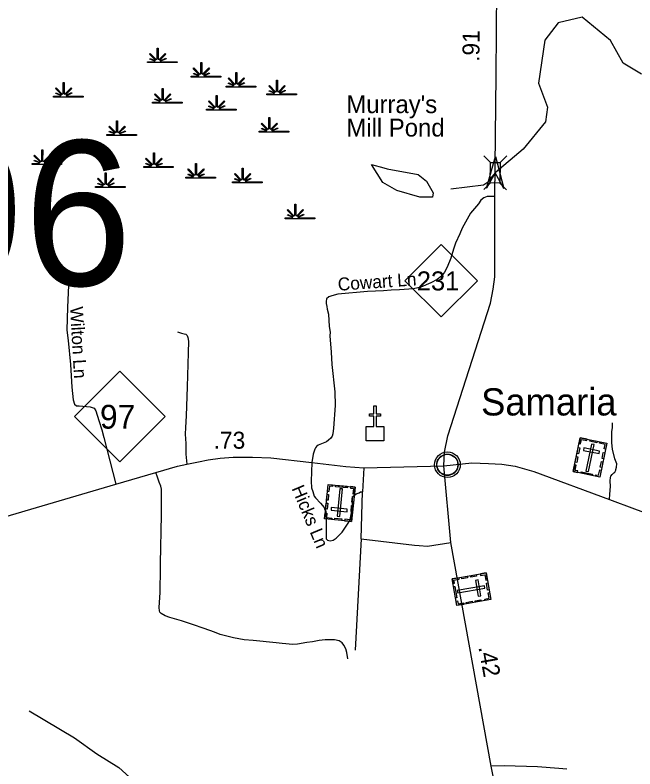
# Model space of a CAD drawing. Extents: x 2220236 to 2384410, y 720751 to 894131.
# Drawn here: x 2240252 to 2244809, y 766678 to 772223 of the extents above; entities that cross this region are included whole.
import ezdxf

# ---------------------------------------------------------------- set-up
doc = ezdxf.new("R2010")
doc.units = 0
doc.layers.add('Default', color=7, linetype='Continuous')

msp = doc.modelspace()

# ---------------------------------------------------------------- linework, layer by layer
at = {"layer": 'Default'}
for p, q in [((2243698.6, 771188.3), (2243747, 771139.1)), ((2243866.8, 771186.9), (2243817.6, 771138.5)), ((2243747, 770988), (2243697.8, 770939.6)), ((2243816, 770987.4), (2243864.4, 770938.2)), ((2242816.7, 768892.5), (2242807.2, 768717.3)), ((2242796.1, 768371.4), (2242807.2, 768717.3)), ((2242796.1, 768371.4), (2242752.9, 767551.3))]:
    msp.add_line(p, q, dxfattribs=at)
for points in [[(2243782.4, 771111.2), (2243790, 771781), (2243793, 772421.1), (2243791, 773115.5), (2243793, 773383.4), (2243759.6, 773678)], [(2244856.2, 771788.5), (2244722.3, 771870), (2244629.2, 772035.9), (2244420.2, 772207.4), (2244245.3, 772165.1), (2244146.3, 772039.2), (2244099.3, 771722.1), (2244167.2, 771546.8), (2244151.2, 771438.9), (2243987.3, 771236.8), (2243782.1, 771061.9), (2243748.1, 771021.8), (2243725.1, 770992.6), (2243695.9, 770973.2), (2243455.2, 770941.5)], [(2243228.6, 770884.2), (2243059, 770932.3), (2242956.1, 770991.4), (2242873.2, 771124.6), (2242963.6, 771100.2), (2242987, 771093.2), (2243215.7, 771050.7), (2243275.7, 771002.5), (2243327, 770915.6), (2243321.1, 770884.3), (2243228.6, 770884.2)], [(2243404.2, 768908.5), (2243410, 769007.2), (2243433.2, 769129.1), (2243746.5, 770104.5), (2243766.8, 770207.6), (2243778.1, 770298.5), (2243779.9, 770888.3), (2243782.4, 771111.2)], [(2243779.9, 770888.3), (2243741.3, 770889.9), (2243723.3, 770889.9), (2243699.3, 770879.6), (2243676.9, 770862.2), (2243659.8, 770835.4), (2243600.3, 770764.9), (2243539.1, 770656.6), (2243521.6, 770614.3), (2243490.1, 770546.2), (2243474.5, 770501.9), (2243455, 770435.9), (2243427.6, 770369.7), (2243407.9, 770331.5), (2243388.1, 770303.4), (2243356.4, 770279.2), (2243308.5, 770254.8), (2243234.9, 770222.1), (2243181, 770209.8), (2243077.1, 770201), (2243017.1, 770200.4), (2242961.2, 770194), (2242843.3, 770191), (2242625.6, 770171.3), (2242579.7, 770158.8), (2242557.8, 770150.7), (2242541.9, 770136.6), (2242538.1, 770116.5), (2242538.1, 770100.5), (2242544.3, 770080.6), (2242546.5, 770058.7), (2242556.7, 770022.7), (2242561.5, 769932.8), (2242567.8, 769890.9), (2242566.1, 769863), (2242577, 769743), (2242581.7, 769653.1), (2242603.4, 769451.3), (2242604.3, 769351.3), (2242593.5, 769185.4), (2242588, 769143.3), (2242582.1, 769125.4), (2242574.2, 769111.2), (2242556.3, 769095.2), (2242540.5, 769085.1), (2242480.7, 769058.5), (2242468.8, 769050.4), (2242460.8, 769040.3), (2242455, 769030.3), (2242443.2, 768994.3), (2242433.7, 768932.1)], [(2240673.3, 770319.1), (2240645.5, 770234.1), (2240638.6, 770074.6), (2240631.7, 769904.6), (2240642.1, 769828.3), (2240659.4, 769653.1), (2240669.8, 769484.9), (2240678.5, 769393), (2240688.9, 769361.8), (2240702.7, 769349.6), (2240723.5, 769347.9), (2240805, 769341), (2240834.4, 769330.6), (2240846.6, 769311.5), (2240869.1, 769240.4), (2240889.9, 769172.7), (2240903.8, 769115.5), (2240991.9, 768772.1)], [(2241447.4, 769892.6), (2241476.4, 769882.4), (2241495.3, 769879.5), (2241508.3, 769875.2), (2241517, 769866.5), (2241522.8, 769850.5), (2241527.2, 769824.4), (2241525.7, 769738.7), (2241517, 769487.6), (2241511.2, 769275.7), (2241504, 769190.1), (2241502.5, 769140.7), (2241506.9, 769072.5), (2241508.3, 768992.7), (2241515.4, 768919.7)], [(2244622.8, 768660.2), (2244625.6, 768699.5), (2244628.5, 768756.1), (2244627, 768796.8), (2244628.5, 768821.4), (2244632.8, 768831.6), (2244641.5, 768844.6), (2244654.6, 768854.8), (2244660.4, 768860.6), (2244669.1, 768875.1), (2244669.1, 768879.5), (2244673.4, 768898.4), (2244674.9, 768923), (2244660.4, 768957.9), (2244643, 769029), (2244640.1, 769076.9), (2244638.6, 769123.3), (2244640.1, 769161.1), (2244644.4, 769187.2), (2244643, 769223.5)], [(2239633.6, 768371.7), (2240991.9, 768772.1), (2241286.5, 768858.8), (2241447.4, 768905.6), (2241515.4, 768919.7), (2241601.2, 768937.5), (2241672.3, 768952.1), (2241760.7, 768963.7), (2241855, 768970.9), (2241998.6, 768970.9), (2242133.5, 768966.6), (2242433.7, 768932.1), (2242683.3, 768901.3), (2242816.7, 768892.5), (2243404.2, 768908.5)], [(2242433.7, 768932.1), (2242430.3, 768862.2), (2242428.9, 768794.3), (2242431.3, 768746.2), (2242441.5, 768718.4), (2242445.6, 768700.3), (2242451.6, 768684.4), (2242459.8, 768672.5), (2242498.2, 768632.9), (2242524.3, 768601.1), (2242530.5, 768583.2), (2242536.7, 768571.1), (2242538.9, 768543.3), (2242540.2, 768371.3), (2242548.4, 768361.3), (2242568.4, 768355.5), (2242590.4, 768361.6), (2242612.3, 768375.8), (2242657.9, 768418.2), (2242705.2, 768492.7), (2242715, 768512.6), (2242716.9, 768524.6), (2242726.6, 768560.8), (2242732.1, 768630.7), (2242731.8, 768666.7), (2242733.8, 768674.8), (2242743.6, 768686.8), (2242759.5, 768700.9), (2242781.5, 768709), (2242791.4, 768715.2), (2242807.2, 768717.3)], [(2243404.2, 768908.5), (2243610.2, 768928.8), (2243732, 768924.5), (2243830.7, 768920.1), (2243927.4, 768904.4), (2244065.7, 768866.4), (2244622.8, 768660.2), (2244806.9, 768592.1), (2245412.9, 768366.8), (2245599.2, 768318.2), (2245769.6, 768287.7), (2245889, 768269.9), (2246369.1, 768222), (2246940.6, 768169.7), (2247148.1, 768147.9), (2247220.6, 768137.8)], [(2243752.3, 766697.9), (2243456.1, 768342.8), (2243404.2, 768908.5)], [(2242699.2, 767487.5), (2242690.5, 767535.4), (2242683.3, 767561.6), (2242668.8, 767589.1), (2242655.7, 767606.5), (2242635.4, 767621.1), (2242600.6, 767628.3), (2242565.8, 767628.3), (2242532.4, 767626.9), (2242487.5, 767622.5), (2242438.1, 767613.8), (2242397.5, 767608), (2242327.9, 767596.4), (2242293.1, 767593.5), (2242216.2, 767599.3), (2242172.7, 767605.1), (2242001.5, 767622.5), (2241936.3, 767628.3), (2241857.9, 767641.4), (2241759.3, 767666.1), (2241717.2, 767683.5), (2241641.8, 767711.1), (2241557.7, 767740.1), (2241475, 767766.2), (2241389.4, 767792.3), (2241356, 767803.9), (2241327, 767819.9), (2241315.4, 767831.5), (2241314, 767840.2), (2241312.5, 767864.9), (2241319.8, 767975.2), (2241321.2, 768158.1), (2241321.2, 768190), (2241328.5, 768547.1), (2241329.9, 768689.3), (2241328.5, 768735.8), (2241324.1, 768757.6), (2241312.5, 768788), (2241299.5, 768824.3), (2241286.5, 768858.8)], [(2242796.1, 768371.4), (2243188.2, 768324.6), (2243222.4, 768320.9), (2243284.3, 768317.4), (2243456.1, 768342.8)], [(2240355.2, 767104.1), (2240690.1, 766907.5), (2240852.8, 766787.7), (2241015.3, 766689.1), (2241147.7, 766567.9)], [(2244309.2, 766676.5), (2244249.3, 766680), (2244093.2, 766692.1), (2243846.6, 766700.8), (2243752.3, 766697.9)], [(2243864.7, 759641.9), (2243930.1, 759702.3), (2243971.8, 759748.6), (2244043.1, 759833.1), (2244135.7, 759980), (2244188.7, 760122.3), (2244207.7, 760224.5), (2244220.4, 760402.3), (2244214.3, 760650.2), (2244209.5, 761477.9), (2244171.3, 761857.2), (2244130, 762281.7), (2244088.7, 762603.9), (2244012.1, 763641.4), (2243951.6, 764595.7), (2243901.8, 765403.6), (2243865.9, 765885.2), (2243845.9, 766119), (2243807.7, 766418.5), (2243752.3, 766697.9)]]:
    msp.add_lwpolyline(points, dxfattribs=at)
for points in [[(2241226, 771880.4), (2241278.7, 771880.5), (2241280.7, 771884.1), (2241242.4, 771898.9), (2241245.3, 771904.1), (2241283, 771888.3), (2241284.6, 771891.2), (2241240.2, 771935.8), (2241245.3, 771940.9), (2241290.6, 771895.4), (2241297, 771897.8), (2241297, 771980.9), (2241304.2, 771980.9), (2241304.2, 771897.8), (2241310.5, 771895.4), (2241355.8, 771940.9), (2241361, 771935.8), (2241316.5, 771891.2), (2241318.5, 771887.6), (2241359.4, 771906.2), (2241361.9, 771901.2), (2241320.9, 771883.4), (2241322.5, 771880.5), (2241443.5, 771880.4), (2241443.5, 771873.3), (2241226, 771873.3)], [(2241546.5, 771773.4), (2241599.2, 771773.5), (2241601.2, 771777.1), (2241562.9, 771792), (2241565.8, 771797.1), (2241603.5, 771781.4), (2241605.1, 771784.3), (2241560.7, 771828.8), (2241565.8, 771834), (2241611.1, 771788.5), (2241617.5, 771790.9), (2241617.5, 771873.9), (2241624.7, 771873.9), (2241624.7, 771790.9), (2241631, 771788.5), (2241676.3, 771834), (2241681.4, 771828.8), (2241637, 771784.3), (2241639, 771780.7), (2241679.9, 771799.3), (2241682.4, 771794.2), (2241641.4, 771776.4), (2241643, 771773.5), (2241764, 771773.4), (2241764, 771766.3), (2241546.5, 771766.3)], [(2241803.5, 771700.4), (2241856.2, 771700.5), (2241858.2, 771704.1), (2241819.9, 771719), (2241822.8, 771724.1), (2241860.6, 771708.4), (2241862.2, 771711.3), (2241817.7, 771755.8), (2241822.9, 771761), (2241868.1, 771715.5), (2241874.5, 771717.9), (2241874.5, 771800.9), (2241881.7, 771800.9), (2241881.7, 771717.9), (2241888, 771715.5), (2241933.3, 771761), (2241938.5, 771755.8), (2241894, 771711.3), (2241896, 771707.7), (2241936.9, 771726.3), (2241939.4, 771721.3), (2241898.4, 771703.4), (2241900, 771700.5), (2242021.1, 771700.4), (2242021.1, 771693.3), (2241803.5, 771693.3)], [(2240534.4, 771627.1), (2240587.1, 771627.2), (2240589.1, 771630.8), (2240550.8, 771645.6), (2240553.7, 771650.8), (2240591.4, 771635.1), (2240593, 771637.9), (2240548.6, 771682.5), (2240553.7, 771687.6), (2240599, 771642.1), (2240605.4, 771644.5), (2240605.4, 771727.6), (2240612.6, 771727.6), (2240612.6, 771644.5), (2240618.9, 771642.1), (2240664.2, 771687.6), (2240669.4, 771682.5), (2240624.9, 771637.9), (2240626.9, 771634.3), (2240667.8, 771652.9), (2240670.3, 771647.9), (2240629.3, 771630.1), (2240630.9, 771627.2), (2240751.9, 771627.1), (2240751.9, 771620), (2240534.4, 771620)], [(2242103.2, 771644), (2242155.8, 771644.1), (2242157.8, 771647.7), (2242119.6, 771662.5), (2242122.5, 771667.7), (2242160.2, 771651.9), (2242161.8, 771654.8), (2242117.4, 771699.4), (2242122.5, 771704.5), (2242167.8, 771659), (2242174.1, 771661.4), (2242174.1, 771744.5), (2242181.4, 771744.5), (2242181.3, 771661.4), (2242187.7, 771659), (2242233, 771704.5), (2242238.1, 771699.4), (2242193.7, 771654.8), (2242195.7, 771651.2), (2242236.6, 771669.8), (2242239, 771664.8), (2242198, 771647), (2242199.7, 771644.1), (2242320.7, 771644), (2242320.7, 771636.9), (2242103.2, 771636.9)], [(2241263.1, 771583.4), (2241315.8, 771583.5), (2241317.8, 771587.1), (2241279.5, 771601.9), (2241282.4, 771607.1), (2241320.1, 771591.4), (2241321.7, 771594.2), (2241277.3, 771638.8), (2241282.4, 771643.9), (2241327.7, 771598.4), (2241334.1, 771600.8), (2241334.1, 771683.9), (2241341.3, 771683.9), (2241341.3, 771600.8), (2241347.6, 771598.4), (2241392.9, 771643.9), (2241398.1, 771638.8), (2241353.6, 771594.2), (2241355.6, 771590.6), (2241396.5, 771609.2), (2241399, 771604.2), (2241358, 771586.4), (2241359.6, 771583.5), (2241480.6, 771583.4), (2241480.6, 771576.3), (2241263.1, 771576.3)], [(2241659, 771531.4), (2241711.6, 771531.5), (2241713.6, 771535.1), (2241675.4, 771549.9), (2241678.3, 771555.1), (2241716, 771539.4), (2241717.6, 771542.3), (2241673.2, 771586.8), (2241678.3, 771591.9), (2241723.6, 771546.4), (2241729.9, 771548.8), (2241729.9, 771631.9), (2241737.2, 771631.9), (2241737.1, 771548.8), (2241743.5, 771546.4), (2241788.8, 771591.9), (2241793.9, 771586.8), (2241749.5, 771542.3), (2241751.5, 771538.7), (2241792.4, 771557.3), (2241794.8, 771552.2), (2241753.8, 771534.4), (2241755.5, 771531.5), (2241876.5, 771531.4), (2241876.5, 771524.3), (2241659, 771524.3)], [(2240928, 771345.7), (2240980.7, 771345.7), (2240982.7, 771349.4), (2240944.4, 771364.2), (2240947.3, 771369.4), (2240985, 771353.6), (2240986.6, 771356.5), (2240942.2, 771401.1), (2240947.3, 771406.2), (2240992.6, 771360.7), (2240998.9, 771363.1), (2240998.9, 771446.2), (2241006.2, 771446.2), (2241006.2, 771363.1), (2241012.5, 771360.7), (2241057.8, 771406.2), (2241062.9, 771401.1), (2241018.5, 771356.5), (2241020.5, 771352.9), (2241061.4, 771371.5), (2241063.9, 771366.5), (2241022.9, 771348.7), (2241024.5, 771345.7), (2241145.5, 771345.7), (2241145.5, 771338.6), (2240928, 771338.6)], [(2242046.9, 771368.2), (2242099.6, 771368.3), (2242101.6, 771371.9), (2242063.3, 771386.7), (2242066.2, 771391.9), (2242104, 771376.2), (2242105.6, 771379), (2242061.1, 771423.6), (2242066.3, 771428.7), (2242111.5, 771383.2), (2242117.9, 771385.6), (2242117.9, 771468.7), (2242125.1, 771468.7), (2242125.1, 771385.6), (2242131.4, 771383.2), (2242176.7, 771428.7), (2242181.9, 771423.6), (2242137.4, 771379), (2242139.4, 771375.4), (2242180.3, 771394), (2242182.8, 771389), (2242141.8, 771371.2), (2242143.4, 771368.3), (2242264.5, 771368.2), (2242264.5, 771361.1), (2242046.9, 771361.1)], [(2240377, 771131.8), (2240429.6, 771131.9), (2240431.6, 771135.5), (2240393.4, 771150.3), (2240396.3, 771155.5), (2240434, 771139.8), (2240435.6, 771142.6), (2240391.2, 771187.2), (2240396.3, 771192.3), (2240441.6, 771146.8), (2240447.9, 771149.2), (2240447.9, 771232.3), (2240455.2, 771232.3), (2240455.1, 771149.2), (2240461.5, 771146.8), (2240506.8, 771192.3), (2240511.9, 771187.2), (2240467.5, 771142.6), (2240469.5, 771139), (2240510.4, 771157.6), (2240512.8, 771152.6), (2240471.8, 771134.8), (2240473.5, 771131.9), (2240594.5, 771131.8), (2240594.5, 771124.7), (2240377, 771124.7)], [(2241197.9, 771109.3), (2241250.5, 771109.4), (2241252.5, 771113), (2241214.3, 771127.8), (2241217.2, 771133), (2241254.9, 771117.2), (2241256.5, 771120.1), (2241212.1, 771164.7), (2241217.2, 771169.8), (2241262.5, 771124.3), (2241268.8, 771126.7), (2241268.8, 771209.8), (2241276.1, 771209.8), (2241276.1, 771126.7), (2241282.4, 771124.3), (2241327.7, 771169.8), (2241332.8, 771164.7), (2241288.4, 771120.1), (2241290.4, 771116.5), (2241331.3, 771135.1), (2241333.7, 771130.1), (2241292.8, 771112.3), (2241294.4, 771109.4), (2241415.4, 771109.3), (2241415.4, 771102.2), (2241197.9, 771102.2)], [(2243718, 770948.8), (2243783.2, 771183.8), (2243844.2, 770947.7), (2243782.1, 771061.9)], [(2241507.2, 771030.5), (2241559.8, 771030.6), (2241561.8, 771034.2), (2241523.6, 771049), (2241526.5, 771054.2), (2241564.2, 771038.4), (2241565.8, 771041.3), (2241521.3, 771085.9), (2241526.5, 771091), (2241571.8, 771045.5), (2241578.1, 771047.9), (2241578.1, 771131), (2241585.3, 771131), (2241585.3, 771047.9), (2241591.6, 771045.5), (2241637, 771091), (2241642.1, 771085.9), (2241597.7, 771041.3), (2241599.7, 771037.7), (2241640.6, 771056.3), (2241643, 771051.3), (2241602, 771033.5), (2241603.6, 771030.6), (2241724.7, 771030.5), (2241724.7, 771023.4), (2241507.2, 771023.4)], [(2243817.6, 771138.5), (2243816.3, 770987.4), (2243745.7, 770988), (2243747, 771139.1)], [(2240843.7, 770962.9), (2240896.3, 770963), (2240898.3, 770966.6), (2240860.1, 770981.5), (2240863, 770986.6), (2240900.7, 770970.9), (2240902.3, 770973.8), (2240857.9, 771018.3), (2240863, 771023.5), (2240908.3, 770978), (2240914.6, 770980.4), (2240914.6, 771063.4), (2240921.9, 771063.4), (2240921.8, 770980.4), (2240928.2, 770978), (2240973.5, 771023.5), (2240978.6, 771018.3), (2240934.2, 770973.8), (2240936.2, 770970.2), (2240977.1, 770988.8), (2240979.5, 770983.7), (2240938.5, 770965.9), (2240940.2, 770963), (2241061.2, 770962.9), (2241061.2, 770955.8), (2240843.7, 770955.8)], [(2241850.2, 770996.7), (2241902.8, 770996.8), (2241904.8, 771000.4), (2241866.5, 771015.2), (2241869.4, 771020.4), (2241907.2, 771004.7), (2241908.8, 771007.6), (2241864.3, 771052.1), (2241869.5, 771057.2), (2241914.7, 771011.7), (2241921.1, 771014.1), (2241921.1, 771097.2), (2241928.3, 771097.2), (2241928.3, 771014.1), (2241934.6, 771011.7), (2241979.9, 771057.2), (2241985.1, 771052.1), (2241940.6, 771007.6), (2241942.6, 771004), (2241983.5, 771022.6), (2241986, 771017.5), (2241945, 770999.7), (2241946.6, 770996.8), (2242067.7, 770996.7), (2242067.7, 770989.6), (2241850.2, 770989.6)], [(2242238.1, 770732.2), (2242290.8, 770732.2), (2242292.8, 770735.9), (2242254.5, 770750.7), (2242257.4, 770755.9), (2242295.1, 770740.1), (2242296.7, 770743), (2242252.3, 770787.6), (2242257.4, 770792.7), (2242302.7, 770747.2), (2242309, 770749.6), (2242309, 770832.7), (2242316.3, 770832.7), (2242316.3, 770749.6), (2242322.6, 770747.2), (2242367.9, 770792.7), (2242373, 770787.6), (2242328.6, 770743), (2242330.6, 770739.4), (2242371.5, 770758), (2242374, 770753), (2242333, 770735.2), (2242334.6, 770732.2), (2242455.6, 770732.2), (2242455.6, 770725.1), (2242238.1, 770725.1)], [(2243118.4, 770269.4), (2243384.8, 770535.8), (2243651.2, 770269.4), (2243384.8, 770003)], [(2240689.1, 769270.6), (2241022.1, 769603.6), (2241355.1, 769270.6), (2241022.1, 768937.6)], [(2242832.9, 769197.4), (2242889.8, 769197.2), (2242890.3, 769273.3), (2242858.3, 769273.5), (2242858.4, 769289.5), (2242890.4, 769289.3), (2242890.8, 769349.4), (2242906.8, 769349.3), (2242906.4, 769289.2), (2242938.4, 769288.9), (2242938.3, 769273), (2242906.3, 769273.2), (2242905.8, 769197), (2242963.5, 769196.5), (2242962.7, 769090.1), (2242832.1, 769091)], [(2244407.5, 769114.1), (2244602.4, 769073.6), (2244550.5, 768824.3), (2244355.6, 768864.9)], [(2244398.7, 769071.7), (2244409.8, 769069.4), (2244416.4, 769100.9), (2244456.1, 769092.7), (2244458.4, 769103.6), (2244407.5, 769114.1)], [(2244508.3, 769063.2), (2244490, 769067), (2244448.7, 768868.5), (2244467, 768864.7)], [(2244480, 769099), (2244530.8, 769088.5), (2244528.5, 769077.3), (2244477.7, 769087.9)], [(2244593.7, 769031.1), (2244582.6, 769033.4), (2244589.1, 769064.9), (2244549.4, 769073.2), (2244551.7, 769084.1), (2244602.5, 769073.5)], [(2244383.6, 768999.1), (2244392.4, 769041.5), (2244403.6, 769039.2), (2244394.7, 768996.8)], [(2244433.6, 769039.2), (2244429.8, 769020.9), (2244545.1, 768996.9), (2244548.9, 769015.2)], [(2244567.6, 768961.9), (2244576.4, 769004.3), (2244587.6, 769002), (2244578.8, 768959.6)], [(2243353.1, 768928), (2243354.1, 768933.6), (2243355.9, 768940.1), (2243358.8, 768947.3), (2243361.7, 768953.1), (2243365.1, 768958.8), (2243368.8, 768963.9), (2243372.8, 768968.3), (2243377.4, 768972.9), (2243382.9, 768977.5), (2243388.3, 768981.2), (2243393.2, 768984), (2243398.3, 768986.5), (2243403.7, 768988.8), (2243409.4, 768990.6), (2243413.7, 768991.7), (2243418.6, 768992.5), (2243422.7, 768993.2), (2243429, 768993.5), (2243433.5, 768993.4), (2243439.1, 768993.1), (2243444, 768992.4), (2243449, 768991.4), (2243454, 768990), (2243459.1, 768988), (2243465.8, 768985.1), (2243472, 768981.6), (2243477.1, 768978.1), (2243482.3, 768974.1), (2243485.6, 768970.9), (2243489.7, 768966.5), (2243493.6, 768961.8), (2243496.6, 768957.3), (2243499.8, 768952.2), (2243502.2, 768947.1), (2243504.3, 768942.1), (2243505.8, 768937.1), (2243507.1, 768932.5), (2243508.2, 768926.4), (2243508.8, 768921.7), (2243509.1, 768915.7), (2243508.9, 768909.9), (2243508.3, 768904.2), (2243507.4, 768898.8), (2243505.7, 768892.6), (2243503.9, 768886.8), (2243501.6, 768881.7), (2243498.4, 768875.7), (2243495.1, 768870.4), (2243491.7, 768865.7), (2243487.5, 768860.9), (2243482.2, 768856), (2243477.2, 768851.9), (2243472.1, 768848.4), (2243467.8, 768845.9), (2243461, 768842.7), (2243453.9, 768840), (2243447.9, 768838.5), (2243441.3, 768837.2), (2243436.9, 768836.7), (2243432.4, 768836.5), (2243426.8, 768836.5), (2243422.5, 768836.9), (2243416.9, 768837.6), (2243411, 768838.9), (2243406.4, 768840.2), (2243401.2, 768842.1), (2243396.6, 768844.1), (2243392.7, 768846.3), (2243385.9, 768850.4), (2243380.3, 768854.7), (2243375.4, 768859.2), (2243370.9, 768864), (2243367.8, 768868), (2243364.8, 768872.1), (2243360.7, 768879.2), (2243359, 768882.8), (2243357.2, 768886.8), (2243354.7, 768895), (2243353.1, 768902), (2243352.4, 768907.2), (2243352.1, 768913.5), (2243352.1, 768918.2), (2243352.6, 768924.7)], [(2244369.9, 768933.3), (2244378.7, 768975.7), (2244389.8, 768973.4), (2244381, 768931)], [(2244554.1, 768897.4), (2244563, 768939.8), (2244574.1, 768937.4), (2244565.3, 768895)], [(2244388, 768858.2), (2244390.4, 768869.4), (2244368.8, 768873.9), (2244377.1, 768913.5), (2244366.2, 768915.7), (2244355.6, 768864.9)], [(2244414.2, 768864.4), (2244497.3, 768847.1), (2244495, 768835.9), (2244411.9, 768853.2)], [(2244518.1, 768831), (2244520.5, 768842.3), (2244542, 768837.8), (2244550.2, 768877.4), (2244561.1, 768875.1), (2244550.5, 768824.3)], [(2242726.3, 768497.7), (2242528.2, 768517.4), (2242553.4, 768770.8), (2242751.5, 768751.1)], [(2242586.4, 768767.5), (2242585.2, 768756.1), (2242563.3, 768758.2), (2242559.3, 768718), (2242548.3, 768719.1), (2242553.4, 768770.8)], [(2242693.2, 768745.3), (2242608.7, 768753.7), (2242609.9, 768765.1), (2242694.3, 768756.7)], [(2242620.7, 768537.6), (2242639.3, 768535.8), (2242659.4, 768737.6), (2242640.8, 768739.4)], [(2242718.6, 768754.3), (2242717.4, 768742.9), (2242739.3, 768740.7), (2242735.3, 768700.5), (2242746.4, 768699.4), (2242751.5, 768751)], [(2242557.5, 768697.7), (2242553.3, 768654.6), (2242541.9, 768655.8), (2242546.2, 768698.9)], [(2242744.6, 768681.5), (2242740.3, 768638.4), (2242729, 768639.5), (2242733.3, 768682.6)], [(2242551, 768632.1), (2242546.7, 768589), (2242535.4, 768590.2), (2242539.7, 768633.3)], [(2242737.9, 768614.6), (2242733.7, 768571.5), (2242722.3, 768572.6), (2242726.6, 768615.7)], [(2242532.4, 768560.6), (2242543.7, 768559.4), (2242540.5, 768527.4), (2242580.9, 768523.4), (2242579.8, 768512.3), (2242528.1, 768517.5)], [(2242692.4, 768569.4), (2242694.3, 768588), (2242577.1, 768599.7), (2242575.2, 768581.1)], [(2242652.6, 768505), (2242601, 768510.2), (2242602.1, 768521.5), (2242653.7, 768516.4)], [(2242730.6, 768540.8), (2242719.3, 768541.9), (2242716.1, 768509.9), (2242675.7, 768513.9), (2242674.6, 768502.8), (2242726.3, 768497.7)], [(2243715.5, 768119.8), (2243750.2, 767923.8), (2243499.5, 767879.4), (2243464.8, 768075.4)], [(2243599.8, 768099.4), (2243642.5, 768106.9), (2243644.5, 768095.7), (2243601.8, 768088.1)], [(2243672.8, 768112.3), (2243674.8, 768101.1), (2243706.5, 768106.7), (2243713.6, 768066.8), (2243724.5, 768068.7), (2243715.5, 768119.8)], [(2243470.6, 768042.8), (2243481.9, 768044.9), (2243478.1, 768066.5), (2243517.9, 768073.6), (2243515.9, 768084.5), (2243464.8, 768075.5)], [(2243533.6, 768087.6), (2243576.3, 768095.2), (2243578.3, 768084), (2243535.6, 768076.4)], [(2243655.6, 768067.8), (2243637.2, 768064.5), (2243657.8, 767948.6), (2243676.1, 767951.8)], [(2243486.1, 768020.8), (2243500.9, 767937.3), (2243489.7, 767935.3), (2243474.9, 768018.8)], [(2243705.7, 768007.4), (2243702.4, 768025.8), (2243502.7, 767990.4), (2243506, 767972)], [(2243728.4, 768046.9), (2243737.4, 767995.9), (2243726.2, 767993.9), (2243717.2, 768044.9)], [(2243707.5, 767916.2), (2243705.6, 767927.3), (2243737.3, 767933), (2243730.2, 767972.9), (2243741.1, 767974.8), (2243750.2, 767923.7)], [(2243493.7, 767912), (2243505, 767914), (2243508.9, 767892.3), (2243548.7, 767899.4), (2243550.6, 767888.4), (2243499.5, 767879.4)], [(2243568.7, 767903.2), (2243611.3, 767910.7), (2243613.3, 767899.5), (2243570.7, 767892)], [(2243633.6, 767914.7), (2243676.2, 767922.2), (2243678.2, 767911), (2243635.6, 767903.4)]]:
    msp.add_lwpolyline(points, close=True, dxfattribs=at)
for centre, radius in [((2243430.7, 768915.6), 94.3), ((2243430.5, 768915.8), 76.7)]:
    msp.add_circle(centre, radius, dxfattribs=at)

# ---------------------------------------------------------------- texts
for s, height, rotation, p in [('.91', 125, 89.7402, (2243666.2, 771879)), ('Cowart Ln', 95, 3.9585, (2242627.9, 770195.1)), ('Wilton Ln', 95, 273.2161, (2240656.5, 770076.3)), ('Hicks Ln', 95, 292.6991, (2242283.5, 768741.5)), ('.42', 125, 280.2072, (2243658.1, 767573.7))]:
    msp.add_text(s, height=height, rotation=rotation, dxfattribs=at).set_placement(p)
for s, height, p in [("Murray's", 131.23, (2242687.9, 771502.1)), ('Mill Pond', 131.23, (2242687.9, 771329.8)), ('96', 1066.27, (2239525.7, 770233.4)), ('231', 140, (2243205.7, 770197.6)), ('Samaria', 200, (2243678.1, 769277.9)), ('97', 175, (2240876.2, 769180.9)), ('.73', 125, (2241712.2, 769033.4))]:
    msp.add_text(s, height=height, dxfattribs=at).set_placement(p)

doc.saveas('drawing.dxf')
